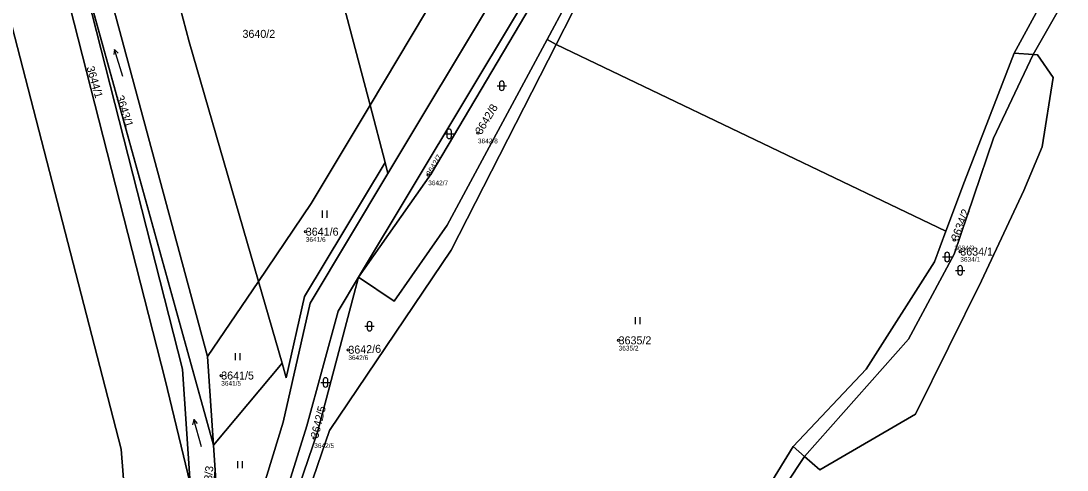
# Model space of a CAD drawing. Extents: x -761174 to -757114, y -1063806 to -1059397.
# Drawn here: x -760149.9 to -759927.6, y -1062146.6 to -1062051.1 of the extents above; entities that cross this region are included whole.
import ezdxf

# ---------------------------------------------------------------- set-up
doc = ezdxf.new("R2010")
doc.units = 0
for name, color, linetype in [('Definiční body', 7, 'Continuous'), ('Hranice parcel', 7, 'Continuous'), ('Parcelní čísla', 7, 'Continuous'), ('Polygon parcely', 7, 'Continuous'), ('Značky kultur', 7, 'Continuous')]:
    doc.layers.add(name, color=color, linetype=linetype)

msp = doc.modelspace()

# ---------------------------------------------------------------- linework, layer by layer
at = {"layer": 'Definiční body'}
for centre in [(-760052.8, -1062074.98), (-760063.36, -1062083.89), (-760089.37, -1062095.91), (-759951.57, -1062097.71), (-759950.32, -1062100.14), (-760080.33, -1062121.02), (-760022.91, -1062119), (-760107.34, -1062126.47), (-760087.58, -1062139.71)]:
    msp.add_circle(centre, 0.25, dxfattribs=at)
at = {"layer": 'Hranice parcel'}
for p, q in [((-760139.59, -1062030.82), (-760108.97, -1062141.29)), ((-760063.96, -1062049.34), (-760075.72, -1062069.05)), ((-760036.2, -1062056.16), (-760038.1, -1062055.1)), ((-759953.37, -1062095.8), (-760036.2, -1062056.16)), ((-759934.83, -1062058.28), (-759938.85, -1062058)), ((-760075.72, -1062069.05), (-760072.53, -1062081.24)), ((-760072.53, -1062081.24), (-760071.92, -1062083.57)), ((-760099.42, -1062106.47), (-760110.26, -1062122.43)), ((-760094.37, -1062123.87), (-760099.42, -1062106.47)), ((-760108.97, -1062141.29), (-760110.26, -1062122.43)), ((-760094.37, -1062123.87), (-760108.97, -1062141.29)), ((-760108.61, -1062146.58), (-760108.97, -1062141.29)), ((-759985.84, -1062141.58), (-759983.44, -1062143.66)), ((-759998.56, -1062166.52), (-759983.44, -1062143.66))]:
    msp.add_line(p, q, dxfattribs=at)
for points in [[(-760075.72, -1062069.05), (-760124.05, -1061886.24), (-760145.06, -1061802.78)], [(-760099.42, -1062106.47), (-760114.18, -1062055.58), (-760142.2, -1061949.6), (-760172.05, -1061835.63)], [(-760110.26, -1062122.43), (-760135.63, -1062028.4), (-760141.46, -1062004.83), (-760146.94, -1061983.64), (-760182.37, -1061848.19)], [(-759876.97, -1061938.51), (-759892.42, -1061960.2), (-759903.25, -1061984.25), (-759921.97, -1062032.77), (-759926.04, -1062042.84), (-759934.83, -1062058.28)], [(-760038.1, -1062055.1), (-760033.91, -1062047.33), (-759978.72, -1061950.02)], [(-760036.2, -1062056.16), (-760025.75, -1062035.71), (-760001.89, -1061995.47), (-759975.91, -1061952.55)], [(-759938.85, -1062058), (-759927.87, -1062037.84), (-759916, -1062010.63), (-759903.73, -1061978.43)], [(-760078.19, -1062105.6), (-760062.71, -1062083.66), (-760002.8, -1061982.5)], [(-760002.8, -1061982.5), (-760013.04, -1061997.91), (-760021.82, -1062011.69), (-760078.19, -1062105.6)], [(-760157.81, -1061984.65), (-760143, -1062034.33), (-760119.24, -1062127.41), (-760113.94, -1062149.4)], [(-760071.92, -1062083.57), (-760026.81, -1062008.39), (-760019.56, -1061997.6)], [(-760208.58, -1062022.63), (-760277.12, -1062047.63), (-760287.15, -1062059.09), (-760286.71, -1062074.9), (-760238.15, -1062218.77), (-760243.02, -1062220.1), (-760182.21, -1062414.05), (-760141.32, -1062378.85), (-760114.19, -1062358.02), (-760113.22, -1062352.44), (-760122.14, -1062274.94), (-760121.9, -1062228.36), (-760128.63, -1062142.08), (-760156.34, -1062034.77), (-760166.16, -1062024.72), (-760190.56, -1062023.61)], [(-760113.94, -1062149.4), (-760115.6, -1062125.13), (-760139.59, -1062030.82)], [(-760105.85, -1062200.98), (-760084.31, -1062138.16), (-760058.52, -1062099.83), (-760036.2, -1062056.16)], [(-760038.1, -1062055.1), (-760059.32, -1062094.52), (-760070.57, -1062110.7), (-760078.19, -1062105.6)], [(-759983.44, -1062143.66), (-759980.14, -1062146.53), (-759959.87, -1062134.71), (-759945.84, -1062106.38), (-759936.8, -1062087.15), (-759932.93, -1062077.89), (-759930.58, -1062063.15), (-759933.91, -1062058.34), (-759934.83, -1062058.28)], [(-759934.83, -1062058.28), (-759943.23, -1062076.05), (-759951.65, -1062100.72), (-759961.32, -1062118.72), (-759983.44, -1062143.66)], [(-759938.85, -1062058), (-759949.4, -1062085.25), (-759953.37, -1062095.8)], [(-760075.72, -1062069.05), (-760088.2, -1062089.96), (-760099.42, -1062106.47)], [(-760072.53, -1062081.24), (-760089.67, -1062109.67), (-760093.53, -1062126.97), (-760094.37, -1062123.87)], [(-760106.71, -1062177.33), (-760094.18, -1062136.41), (-760088.44, -1062111.09), (-760071.92, -1062083.57)], [(-759953.37, -1062095.8), (-759955.83, -1062102.33), (-759970.3, -1062125.12), (-759985.84, -1062141.58)], [(-760078.19, -1062105.6), (-760082.5, -1062112.77), (-760089.13, -1062137.18), (-760105.43, -1062189.41)], [(-760099.62, -1062175.81), (-760086.86, -1062138.48), (-760078.19, -1062105.6)], [(-760100.1, -1062326.69), (-760086.16, -1062315.83), (-760067.12, -1062276.43), (-760015.51, -1062195.1), (-760007.7, -1062177.59), (-760004.67, -1062171.47), (-759996.19, -1062158.39), (-759985.84, -1062141.58)]]:
    msp.add_lwpolyline(points, dxfattribs=at)
at = {"layer": 'Polygon parcely'}
for points in [[(-760055.15, -1062025.41), (-760074.71, -1061936.12), (-760085.88, -1061891.1), (-760115.08, -1061766.3), (-760145.06, -1061802.78), (-760124.05, -1061886.24), (-760075.72, -1062069.05), (-760063.96, -1062049.34)], [(-760124.05, -1061886.24), (-760145.06, -1061802.78), (-760172.05, -1061835.63), (-760142.2, -1061949.6), (-760114.18, -1062055.58), (-760099.42, -1062106.47), (-760088.2, -1062089.96), (-760075.72, -1062069.05)], [(-760114.18, -1062055.58), (-760142.2, -1061949.6), (-760172.05, -1061835.63), (-760182.37, -1061848.19), (-760146.94, -1061983.64), (-760141.46, -1062004.83), (-760135.63, -1062028.4), (-760110.26, -1062122.43), (-760099.42, -1062106.47)], [(-760108.97, -1062141.29), (-760110.26, -1062122.43), (-760135.63, -1062028.4), (-760141.46, -1062004.83), (-760146.94, -1061983.64), (-760182.37, -1061848.19), (-760186.96, -1061855.3), (-760151.84, -1061984.03), (-760139.59, -1062030.82)], [(-760119.24, -1062127.41), (-760113.94, -1062149.4), (-760115.6, -1062125.13), (-760139.59, -1062030.82), (-760151.84, -1061984.03), (-760186.96, -1061855.3), (-760192.93, -1061863.14), (-760191.96, -1061866.48), (-760188.05, -1061861.69), (-760157.81, -1061984.65), (-760143, -1062034.33)], [(-759832.69, -1062004.44), (-759891.84, -1061982.9), (-759872.71, -1061940.25), (-759876.97, -1061938.51), (-759892.42, -1061960.2), (-759903.25, -1061984.25), (-759921.97, -1062032.77), (-759926.04, -1062042.84), (-759934.83, -1062058.28), (-759933.91, -1062058.34), (-759930.58, -1062063.15), (-759932.93, -1062077.89), (-759936.8, -1062087.15), (-759945.84, -1062106.38), (-759959.87, -1062134.71), (-759980.14, -1062146.53), (-759983.44, -1062143.66), (-759998.56, -1062166.52), (-759991.81, -1062172.01), (-759902.67, -1062196.46), (-759900.77, -1062196.98), (-759889.95, -1062161.71), (-759870.91, -1062107.09), (-759829.45, -1062005.62)], [(-760033.91, -1062047.33), (-759978.72, -1061950.02), (-759981.79, -1061947.25), (-760002.8, -1061982.5), (-760062.71, -1062083.66), (-760078.19, -1062105.6), (-760070.57, -1062110.7), (-760059.32, -1062094.52), (-760038.1, -1062055.1)], [(-760001.89, -1061995.47), (-759975.91, -1061952.55), (-759978.72, -1061950.02), (-760033.91, -1062047.33), (-760038.1, -1062055.1), (-760036.2, -1062056.16), (-760025.75, -1062035.71)], [(-759903.73, -1061978.43), (-759960.68, -1061951.18), (-759965.05, -1061956.68), (-759975.91, -1061952.55), (-760001.89, -1061995.47), (-760025.75, -1062035.71), (-760036.2, -1062056.16), (-759953.37, -1062095.8), (-759949.4, -1062085.25), (-759938.85, -1062058), (-759927.87, -1062037.84), (-759916, -1062010.63)], [(-760013.04, -1061997.91), (-760021.82, -1062011.69), (-760078.19, -1062105.6), (-760062.71, -1062083.66), (-760002.8, -1061982.5)], [(-760075.72, -1062069.05), (-760072.53, -1062081.24), (-760071.92, -1062083.57), (-760026.81, -1062008.39), (-760019.56, -1061997.6), (-760023.3, -1061984.12), (-760030.23, -1061995.06), (-760048.54, -1062021.29), (-760061.35, -1062044.96), (-760063.96, -1062049.34)], [(-760208.58, -1062022.63), (-760277.12, -1062047.63), (-760287.15, -1062059.09), (-760286.71, -1062074.9), (-760238.15, -1062218.77), (-760243.02, -1062220.1), (-760182.21, -1062414.05), (-760141.32, -1062378.85), (-760114.19, -1062358.02), (-760113.22, -1062352.44), (-760122.14, -1062274.94), (-760121.9, -1062228.36), (-760128.63, -1062142.08), (-760156.34, -1062034.77), (-760166.16, -1062024.72), (-760190.56, -1062023.61)], [(-760108.61, -1062146.58), (-760108.97, -1062141.29), (-760139.59, -1062030.82), (-760115.6, -1062125.13), (-760113.94, -1062149.4), (-760110.63, -1062169.79)], [(-760004.67, -1062171.47), (-759996.19, -1062158.39), (-759985.84, -1062141.58), (-759970.3, -1062125.12), (-759955.83, -1062102.33), (-759953.37, -1062095.8), (-760036.2, -1062056.16), (-760058.52, -1062099.83), (-760084.31, -1062138.16), (-760105.85, -1062200.98), (-760109.68, -1062224.55), (-760108.99, -1062255.25), (-760105.48, -1062292.13), (-760100.1, -1062326.69), (-760086.16, -1062315.83), (-760067.12, -1062276.43), (-760015.51, -1062195.1), (-760007.7, -1062177.59)], [(-760058.52, -1062099.83), (-760036.2, -1062056.16), (-760038.1, -1062055.1), (-760059.32, -1062094.52), (-760070.57, -1062110.7), (-760078.19, -1062105.6), (-760086.86, -1062138.48), (-760099.62, -1062175.81), (-760105.85, -1062200.98), (-760084.31, -1062138.16)], [(-759953.37, -1062095.8), (-759955.83, -1062102.33), (-759970.3, -1062125.12), (-759985.84, -1062141.58), (-759983.44, -1062143.66), (-759961.32, -1062118.72), (-759951.65, -1062100.72), (-759943.23, -1062076.05), (-759934.83, -1062058.28), (-759938.85, -1062058), (-759949.4, -1062085.25)], [(-759932.93, -1062077.89), (-759930.58, -1062063.15), (-759933.91, -1062058.34), (-759934.83, -1062058.28), (-759943.23, -1062076.05), (-759951.65, -1062100.72), (-759961.32, -1062118.72), (-759983.44, -1062143.66), (-759980.14, -1062146.53), (-759959.87, -1062134.71), (-759945.84, -1062106.38), (-759936.8, -1062087.15)], [(-760099.42, -1062106.47), (-760094.37, -1062123.87), (-760093.53, -1062126.97), (-760089.67, -1062109.67), (-760072.53, -1062081.24), (-760075.72, -1062069.05), (-760088.2, -1062089.96)], [(-760093.53, -1062126.97), (-760094.37, -1062123.87), (-760108.97, -1062141.29), (-760108.61, -1062146.58), (-760107.41, -1062167.63), (-760106.71, -1062177.33), (-760094.18, -1062136.41), (-760088.44, -1062111.09), (-760071.92, -1062083.57), (-760072.53, -1062081.24), (-760089.67, -1062109.67)], [(-760110.26, -1062122.43), (-760108.97, -1062141.29), (-760094.37, -1062123.87), (-760099.42, -1062106.47)], [(-760082.5, -1062112.77), (-760089.13, -1062137.18), (-760105.43, -1062189.41), (-760099.62, -1062175.81), (-760086.86, -1062138.48), (-760078.19, -1062105.6)], [(-760010.95, -1062192.52), (-760005.28, -1062179), (-759998.56, -1062166.52), (-759983.44, -1062143.66), (-759985.84, -1062141.58), (-759996.19, -1062158.39), (-760004.67, -1062171.47), (-760007.7, -1062177.59), (-760015.51, -1062195.1), (-760067.12, -1062276.43), (-760086.16, -1062315.83), (-760100.1, -1062326.69), (-760098.41, -1062337.59), (-760083.35, -1062318.15), (-760064.78, -1062278.38), (-760046.65, -1062249.38), (-760013.6, -1062197.68)]]:
    msp.add_lwpolyline(points, close=True, dxfattribs=at)
for points in [[(-759821.2, -1061820), (-759879.88, -1061937.11), (-759894.98, -1061959.08), (-759903.73, -1061978.43), (-759916, -1062010.63), (-759927.87, -1062037.84), (-759938.85, -1062058), (-759934.83, -1062058.28), (-759926.04, -1062042.84), (-759921.97, -1062032.77), (-759903.25, -1061984.25), (-759892.42, -1061960.2), (-759876.97, -1061938.51), (-759819.12, -1061821.56)], [(-760113.08, -1062330.04), (-760116.85, -1062293.88), (-760121.06, -1062255.88), (-760120.27, -1062225.17), (-760116.76, -1062197.25), (-760113.94, -1062149.4), (-760119.24, -1062127.41), (-760143, -1062034.33), (-760157.81, -1061984.65), (-760186.22, -1061886.36), (-760194.21, -1061899.88), (-760215.36, -1061925.94), (-760219.08, -1061932.52), (-760217.97, -1061941.47), (-760198.33, -1062014.17), (-760190.56, -1062023.61), (-760166.16, -1062024.72), (-760156.34, -1062034.77), (-760128.63, -1062142.08), (-760121.9, -1062228.36), (-760122.14, -1062274.94), (-760113.22, -1062352.44)], [(-760102.43, -1062344.55), (-760108.64, -1062292.91), (-760112.31, -1062255.4), (-760112.92, -1062224.77), (-760108.65, -1062199.73), (-760105.43, -1062189.41), (-760089.13, -1062137.18), (-760082.5, -1062112.77), (-760078.19, -1062105.6), (-760021.82, -1062011.69), (-760013.04, -1061997.91), (-760002.8, -1061982.5), (-759981.79, -1061947.25), (-759978.84, -1061942.51), (-759957.11, -1061907.61)], [(-759974.79, -1061923.48), (-759987.88, -1061943.33), (-760006.79, -1061975.1), (-760007.93, -1061977.15), (-760018.04, -1061995.34), (-760019.56, -1061997.6), (-760026.81, -1062008.39), (-760071.92, -1062083.57), (-760088.44, -1062111.09), (-760094.18, -1062136.41), (-760106.71, -1062177.33), (-760108.47, -1062183.07), (-760113.1, -1062198.21), (-760117.07, -1062225), (-760116.47, -1062255.63), (-760112.88, -1062293.18), (-760106.98, -1062354.42)]]:
    msp.add_lwpolyline(points, dxfattribs=at)
at = {"layer": 'Značky kultur'}
for p, q in [((-760129.98, -1062057.22), (-760130.18, -1062058.3)), ((-760128.23, -1062062.96), (-760129.98, -1062057.22)), ((-760129.98, -1062057.22), (-760129.22, -1062058.01)), ((-760048.74, -1062064.92), (-760046.74, -1062064.92)), ((-760048.24, -1062064.42), (-760048.24, -1062065.42)), ((-760047.24, -1062065.42), (-760047.24, -1062064.42)), ((-760059.93, -1062075.13), (-760057.93, -1062075.13)), ((-760059.43, -1062074.63), (-760059.43, -1062075.63)), ((-760058.43, -1062075.63), (-760058.43, -1062074.63)), ((-760085.85, -1062092.94), (-760085.85, -1062091.44)), ((-760084.85, -1062092.94), (-760084.85, -1062091.44)), ((-759953.63, -1062100.79), (-759953.63, -1062101.79)), ((-759952.63, -1062101.79), (-759952.63, -1062100.79)), ((-759954.13, -1062101.29), (-759952.13, -1062101.29)), ((-759951.36, -1062104.13), (-759949.36, -1062104.13)), ((-759950.86, -1062103.63), (-759950.86, -1062104.63)), ((-759949.86, -1062104.63), (-759949.86, -1062103.63)), ((-760019.31, -1062115.54), (-760019.31, -1062114.04)), ((-760018.31, -1062115.54), (-760018.31, -1062114.04)), ((-760076.82, -1062116), (-760074.82, -1062116)), ((-760076.32, -1062115.5), (-760076.32, -1062116.5)), ((-760075.32, -1062116.5), (-760075.32, -1062115.5)), ((-760104.29, -1062123.22), (-760104.29, -1062121.72)), ((-760103.29, -1062123.22), (-760103.29, -1062121.72)), ((-760085.67, -1062127.43), (-760085.67, -1062128.43)), ((-760084.67, -1062128.43), (-760084.67, -1062127.43)), ((-760086.17, -1062127.93), (-760084.17, -1062127.93)), ((-760113.19, -1062135.83), (-760113.41, -1062136.91)), ((-760111.54, -1062141.59), (-760113.19, -1062135.83)), ((-760113.19, -1062135.83), (-760112.44, -1062136.63)), ((-760103.82, -1062146.16), (-760103.82, -1062144.66)), ((-760102.82, -1062146.16), (-760102.82, -1062144.66))]:
    msp.add_line(p, q, dxfattribs=at)
for centre, start, end in [((-760047.74, -1062064.42), 0, 180), ((-760047.74, -1062065.42), 180, 359.9879), ((-760058.93, -1062074.63), 0, 180), ((-760058.93, -1062075.63), 180, 359.9879), ((-759953.13, -1062100.79), 0, 180), ((-759953.13, -1062101.79), 180, 359.9879), ((-759950.36, -1062103.63), 0, 180), ((-759950.36, -1062104.63), 180, 359.9879), ((-760075.82, -1062115.5), 0, 180), ((-760075.82, -1062116.5), 180, 359.9879), ((-760085.17, -1062127.43), 0, 180), ((-760085.17, -1062128.43), 180, 359.9879)]:
    msp.add_arc(centre, 0.5, start, end, dxfattribs=at)

# ---------------------------------------------------------------- texts
at = {"layer": 'Definiční body'}
for s, p in [('3642/8', (-760052.8, -1062077.14)), ('3642/7', (-760063.36, -1062086.05)), ('3641/6', (-760089.37, -1062098.07)), ('3634/2', (-759951.57, -1062099.87)), ('3634/1', (-759950.32, -1062102.3)), ('3635/2', (-760022.91, -1062121.16)), ('3642/6', (-760080.33, -1062123.18)), ('3641/5', (-760107.34, -1062128.63)), ('3642/5', (-760087.58, -1062141.87))]:
    msp.add_text(s, height=1, dxfattribs=at).set_placement(p)
at = {"layer": 'Parcelní čísla'}
for s, p in [('3640/2', (-760102.82, -1062054.74)), ('3641/6', (-760089.37, -1062096.76)), ('3634/1', (-759950.32, -1062100.99)), ('3635/2', (-760022.91, -1062119.85)), ('3641/5', (-760107.34, -1062127.32))]:
    msp.add_text(s, height=1.7, dxfattribs=at).set_placement(p)
for s, height, rotation, p in [('3644/1', 1.7, 286, (-760135.98, -1062061.02)), ('3643/1', 1.7, 288, (-760129.72, -1062067.27)), ('3642/8', 1.7, 59, (-760052.07, -1062075.42)), ('3642/7', 1.19, 60, (-760062.84, -1062084.19)), ('3634/2', 1.7, 69, (-759950.78, -1062098.01)), ('3642/6', 1.7, 2, (-760080.3, -1062121.87)), ('3642/5', 1.7, 76, (-760086.76, -1062139.92)), ('3643/3', 1.7, 84, (-760109.71, -1062152.68))]:
    msp.add_text(s, height=height, rotation=rotation, dxfattribs=at).set_placement(p)

doc.saveas('drawing.dxf')
